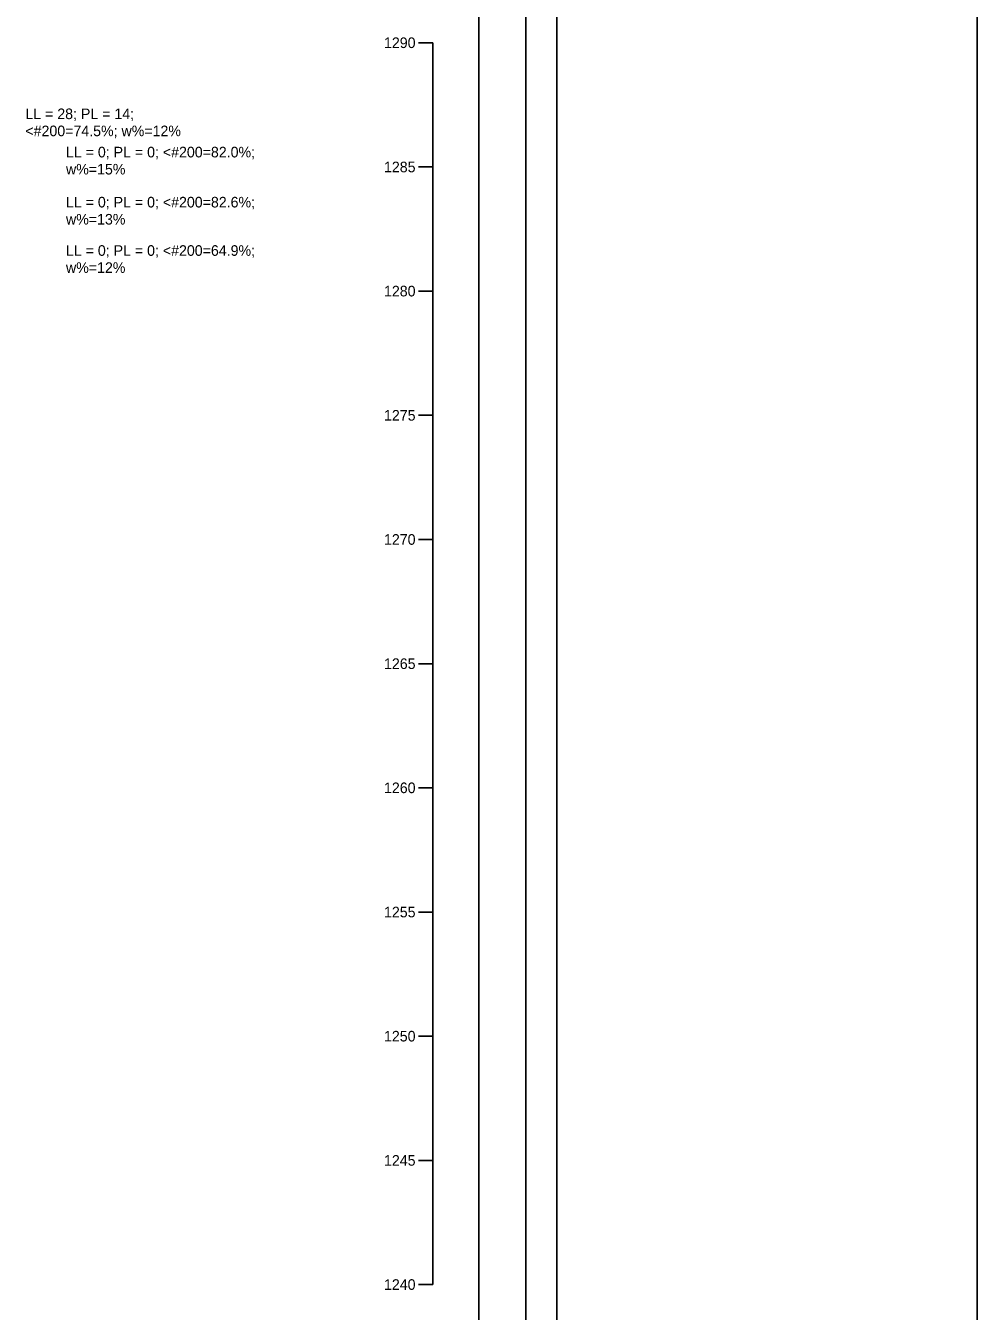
# Model space of a CAD drawing. Extents: x -6 to 173, y 24 to 64.
# Drawn here: x 161.44 to 172.58, y 35.65 to 50.69 of the extents above; entities that cross this region are included whole.
import ezdxf

# ---------------------------------------------------------------- set-up
doc = ezdxf.new("R2010")
doc.units = 0
for name, color, linetype in [('S', 7, 'Continuous'), ('SHT_Plot_Shape_Full', 7, 'Continuous'), ('SHT_Plot_Shape_Half', 7, 'Continuous'), ('SHT_Sheet_Border', 7, 'Continuous')]:
    doc.layers.add(name, color=color, linetype=linetype)

msp = doc.modelspace()

# ---------------------------------------------------------------- linework, layer by layer
msp.add_line((166.204, 35.958), (166.204, 50.493))
for points in [[(166.204, 50.493), (166.037, 50.493)], [(166.204, 49.039), (166.037, 49.039)], [(166.204, 47.586), (166.037, 47.586)], [(166.204, 46.132), (166.037, 46.132)], [(166.204, 44.679), (166.037, 44.679)], [(166.204, 43.225), (166.037, 43.225)], [(166.204, 41.772), (166.037, 41.772)], [(166.204, 40.318), (166.037, 40.318)], [(166.204, 38.865), (166.037, 38.865)], [(166.204, 37.411), (166.037, 37.411)], [(166.204, 35.958), (166.037, 35.958)]]:
    msp.add_lwpolyline(points)
at = {"layer": 'S'}
msp.add_lwpolyline([(-6.024, 64.421), (172.576, 64.421), (172.576, 25.783), (-6.024, 25.783)], close=True, dxfattribs=at)
at = {"layer": 'SHT_Plot_Shape_Full'}
msp.add_lwpolyline([(131.656, 53.971), (167.656, 53.971), (167.656, 29.971), (131.656, 29.971)], close=True, dxfattribs=at)
at = {"layer": 'SHT_Plot_Shape_Half'}
msp.add_lwpolyline([(133.294, 53.146), (167.294, 53.146), (167.294, 31.146), (133.294, 31.146)], close=True, dxfattribs=at)
at = {"layer": 'SHT_Sheet_Border'}
msp.add_lwpolyline([(135.244, 52.646), (166.744, 52.646), (166.744, 31.646), (135.244, 31.646)], close=True, dxfattribs=at)

# ---------------------------------------------------------------- texts
for s, p in [('1290', (165.633, 50.431)), ('LL = 28; PL = 14;', (161.436, 49.599)), ('<#200=74.5%; w%=12%', (161.436, 49.399)), ('LL = 0; PL = 0; <#200=82.0%;', (161.911, 49.151)), ('w%=15%', (161.911, 48.951)), ('1285', (165.633, 48.977)), ('LL = 0; PL = 0; <#200=82.6%;', (161.911, 48.565)), ('w%=13%', (161.911, 48.365)), ('LL = 0; PL = 0; <#200=64.9%;', (161.911, 47.999)), ('w%=12%', (161.911, 47.799)), ('1280', (165.633, 47.524)), ('1275', (165.633, 46.07)), ('1270', (165.633, 44.617)), ('1265', (165.633, 43.163)), ('1260', (165.633, 41.71)), ('1255', (165.633, 40.256)), ('1250', (165.633, 38.803)), ('1245', (165.633, 37.349)), ('1240', (165.633, 35.896))]:
    msp.add_text(s, height=0.124).set_placement(p)

doc.saveas('drawing.dxf')
